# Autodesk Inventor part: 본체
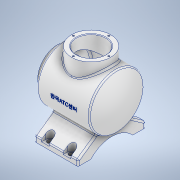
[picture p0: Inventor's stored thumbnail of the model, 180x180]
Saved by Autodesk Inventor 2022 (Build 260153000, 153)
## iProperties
Created: 2023-04
Part Number: 본체
Material: 알루미늄 6061
Document SubType Name: Modeling
Designer: ADMIN_PC
Density: 2.7 g/cm^3
Appearance: 알루미늄 - 평지
Mass: 1296.71 g
Surface Area: 1060.45 cm^2
Volume: 480.264 cm^3
Author: ADMIN_PC
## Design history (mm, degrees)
sketch "스케치1"
  geometry: L1 (-85.64, 0)-(92.662, 0) reference; L2 (0, -20.644)-(0, 92.638) reference; L3 (-48.168, 50)-(48.168, 50); L4 (48.168, 50)-(48.168, 0); L5 (48.168, 0)-(-48.168, 0); L6 (-48.168, 0)-(-48.168, 50); L7 (-48.168, 0)-(-60.168, 0); L8 (-60.168, 0)-(-60.168, 36); L9 (-60.168, 36)-(-48.168, 36); L10 (-48.168, 36)-(-48.168, 0); L11 (48.168, 0)-(59.832, 0); A1 r 113 centre (-53.168, 0) between (59.744, -4.46) and (32.36, 73.851); 3 further points
  constraints: 18 end point, 4 parallel, 4 point on circle, 3 point on line, 2 horizontal, 2 perpendicular, 1 centre point, 1 other
  dimensions: "d1" = 113 radius of A1; "d2" = 108 distance from line of L11.end L6; "d3" = 100 diameter of L3 L5; "d4" = 72 diameter of L9 L5; "d5" = 120 distance from line of L11.end L8
revolve "회전1" sketch "스케치1" stored, may be unused: angle "d6" = 90 deg
sketch "스케치2"
  geometry: L1 (60.168, 36)-(60.168, -36) reference; L2 (82.8, 0)-(-54.4, 0) reference; C1 r 36 at (-1.832, 0); 1 further point
  constraints: 1 centre point, 1 point on line
  dimensions: "d7" = 62 distance from line of L1 C1.centre; "d8" = 72 diameter of C1
extrude "돌출1" join sketch "스케치2" distance "d9" = 65; taper "d10" = 0 deg
node "작업 평면1"
sketch "스케치3"
  geometry: L1 (40.168, 62)-(-39.832, 62); L2 (-39.832, 62)-(-39.832, -62); L3 (-39.832, -62)-(40.168, -62); L4 (40.168, -62)-(40.168, 62); L5 (60.168, 36)-(60.168, -36) reference; L6 (84.168, 0)-(-83.832, 0) reference; 1 further point
  constraints: 8 end point, 2 parallel, 1 horizontal, 1 perpendicular, 1 other
  dimensions: "d12" = 20 distance between parallel lines of L5 L4; "d13" = 124 distance of L3.end L1.start; "d14" = 80 distance between parallel lines of L2 L4
extrude "돌출2" join sketch "스케치3" distance "d15" = 10; taper "d16" = 0 deg
sketch "스케치4"
  geometry: L1 (124, 10)-(0, 10) reference; L2 (0, 10)-(49.774, 44.852); L3 (49.774, 44.852)-(74.226, 44.852); L4 (124, 0)-(124, 10) reference; L5 (74.226, 44.852)-(124, 10); L6 (0, 0)-(0, 10) reference; 1 further point
  constraints: 6 end point, 1 horizontal
  dimensions: "d17" = 55 deg angle of L5 L4; "d18" = 55 deg angle of L2 L6; "d19" = 34.85185 distance between parallel lines of L1 L3
extrude "돌출3" join sketch "스케치4" distance "d20" = 80; taper "d21" = 0 deg
sketch "스케치5"
  geometry: L1 (62, 153.549)-(62, -9.987); L2 (23.5, 0)-(100.5, 0); L3 (100.5, 0)-(100.5, 17); L4 (100.5, 17)-(23.5, 17); L5 (23.5, 17)-(23.5, 0); L6 (124, 0)-(0, 0) reference; A1 r 52.096 centre (62, -35.096) between (100.5, 0) and (23.5, 0); 3 further points
  constraints: 10 end point, 2 parallel, 2 point on circle, 1 centre point, 1 collinear, 1 horizontal, 1 perpendicular, 1 point on line, 1 vertical, 1 other
  dimensions: "d22" = 77 distance between parallel lines of L3 L5; "d23" = 17 distance between parallel lines of L2 L4; "d24" = 52.09559 radius of A1
extrude "돌출4" cut sketch "스케치5" extent not by distance; stored distance "d25" = 0; taper "d26" = 0 deg
node "작업 평면3"
sketch "스케치6"
  geometry: L1 (-19.832, -54)-(-19.832, -74.505); L2 (-12.832, -54)-(-12.832, -74.505); L3 (-26.832, -74.505)-(-26.832, -54); L4 (-39.832, -62)-(40.168, -62) reference; L5 (-39.832, -38.5)-(-39.832, -62) reference; L6 (84.168, 0)-(-83.832, 0) reference; L7 (0, -111.2)-(0, 90.867) reference; L8 (20.168, -54)-(20.168, -74.505); L9 (13.168, -54)-(13.168, -74.505); L10 (27.168, -74.505)-(27.168, -54); L11 (20.168, 54)-(20.168, 74.505); L12 (27.168, 74.505)-(27.168, 54); L13 (-19.832, 54)-(-19.832, 74.505); L14 (-26.832, 74.505)-(-26.832, 54); L15 (13.168, 54)-(13.168, 74.505); L16 (-12.832, 54)-(-12.832, 74.505); A1 r 7 centre (-19.832, -54) between (-12.832, -54) and (-26.832, -54); A2 r 7 centre (-19.832, -74.505) between (-26.832, -74.505) and (-12.832, -74.505); A3 r 7 centre (20.168, -54) between (27.168, -54) and (13.168, -54); A4 r 7 centre (20.168, -74.505) between (13.168, -74.505) and (27.168, -74.505); A5 r 7 centre (20.168, 54) between (13.168, 54) and (27.168, 54); A6 r 7 centre (-19.832, 54) between (-26.832, 54) and (-12.832, 54); A7 r 7 centre (20.168, 74.505) between (27.168, 74.505) and (13.168, 74.505); A8 r 7 centre (-19.832, 74.505) between (-12.832, 74.505) and (-26.832, 74.505); 5 further points
  constraints: 32 end point, 16 point on circle, 14 symmetric about line, 8 centre point, 8 tangent, 2 midpoint, 2 parallel, 2 vertical, 4 other
  dimensions: "d28" = 14 distance between parallel lines of L2 L3; "d29" = 8 distance from line of L4 L1.start; "d30" = 20 distance between parallel lines of L5 L1; "d31" = 20.50493 distance of L3.start L3.end; "d32" = 8 distance from line of L4 L8.start; "d33" = 14 distance between parallel lines of L9 L10; "d34" = 40 distance between parallel lines of L8 L1; "d35" = 20.50493 distance of L10.start L10.end
extrude "돌출5" cut sketch "스케치6" distance "d36" = 20.50493 (= d35); taper "d37" = 0 deg
sketch "스케치7"
  geometry: L1 (-84.168, 0)-(83.832, 0) reference; L2 (0, -105.4)-(0, 93.4) reference; L3 (-60.168, -36)-(-60.168, 36) reference; L4 (-60.168, 0)-(-41.168, 0); L5 (-41.168, 0)-(-41.168, 27); L6 (-41.168, 27)-(-60.168, 27); L7 (-60.168, 27)-(-60.168, 0); L8 (-41.168, 0)-(43.718, 0); L9 (43.718, 0)-(43.718, 43); L10 (43.718, 43)-(-41.168, 43); L11 (-41.168, 43)-(-41.168, 0); L12 (43.718, 0)-(52.832, 0); A1 r 113 centre (-53.168, 0) between (48.168, -50) and (48.168, 50) reference; A2 r 106 centre (-53.168, 0) between (41.891, -46.903) and (41.891, 46.903); 5 further points
  constraints: 18 end point, 4 parallel, 4 point on circle, 2 horizontal, 2 perpendicular, 1 centre point, 1 collinear, 1 midpoint
  dimensions: "d38" = 7 radial gap between concentric circles of A1 A2; "d39" = 19 distance between parallel lines of L11 L3; "d40" = 54 diameter of L6 L1; "d41" = 86 diameter of L10 L1
revolve "회전2" sketch "스케치7" stored, may be unused: angle "d42" = 90 deg
sketch "스케치8"
  geometry: C1 r 36 at (0, 0) reference; C2 r 27 at (0, 0); 1 further point
  constraints: 1 centre point
  dimensions: "d43" = 54 diameter of C2
extrude "돌출6" cut sketch "스케치8" distance "d44" = 65; taper "d45" = 0 deg
sketch "스케치9" dims "d46" = 65
  geometry: L1 (0, -105.4)-(0, 93.4) reference; 3 further points
  constraints: 1 coincident, 1 point on line, 1 vertical alignment, 2 other
hole "구멍1" sketch "스케치9" at (0, 32.5) diameter "d47" = 3.242; stored, may be unused: countersink angle "d51" = 90 deg, drill point angle "d53" = 118 deg; dims "d48" = 8, "d49" = 4, "d50" = 2, "d52" = 10
sketch "스케치10" dims "d57" = 65
  geometry: L1 (0, 0)-(0, 34.763); C1 r 27 at (0, 0) reference; 2 further points
  constraints: 2 end point, 1 point on line, 1 vertical, 1 vertical alignment, 2 other
hole "구멍2" sketch "스케치10" at (0, 32.5) diameter "d58" = 3.242; stored, may be unused: countersink angle "d62" = 90 deg, drill point angle "d64" = 118 deg; dims "d59" = 8, "d60" = 4, "d61" = 2, "d63" = 10
fillet "모깎기1" dims "d68" = 3
chamfer "모따기1" distance "d69" = 1; stored, may be unused: second distance "d70" = 2, angle "d71" = 45 deg
sketch "스케치11"
  geometry: A1 r 7 centre (-20.168, -54) between (-13.168, -54) and (-27.168, -54) reference; A2 r 7 centre (19.832, -54) between (26.832, -54) and (12.832, -54) reference; A3 r 7 centre (19.832, 54) between (12.832, 54) and (26.832, 54) reference; A4 r 7 centre (-20.168, 54) between (-27.168, 54) and (-13.168, 54) reference; 5 further points
  constraints: 4 coincident
hole "구멍3" sketch "스케치11" at (19.832, 54), (-20.168, 54), (-20.168, -54), (19.832, -54) diameter "d72" = 9; stored, may be unused: countersink angle "d76" = 90 deg, drill point angle "d78" = 118 deg; dims "d73" = 8, "d74" = 4, "d75" = 2, "d77" = 10
node "작업 평면4"
sketch "스케치12"
  geometry: L1 (-60.168, -36)-(-60.168, 36) reference; L2 (-84.168, 0)-(83.832, 0) reference; 2 further points
  constraints: 1 point on line, 1 other
  dimensions: "d79" = 62 distance from line of L1 point (1.832, 0)
feature "엠보싱1" sketch "스케치12" dims "d1" = 113, "d2" = 108, "d3" = 100, "d4" = 72, "d5" = 120, "d80" = 0.5, "d81" = 0
node "솔리드1"
pattern_circular "원형 패턴1" dims angle "d55" = 360 deg
pattern_circular "원형 패턴2" dims angle "d66" = 360 deg
feature "A9D066F2-1C7D-4E18-AEED-F7BC21143FA4" dims "d72" = 9, "d73" = 8, "d74" = 4, "d75" = 2, "d76" = 90 deg, "d77" = 10, "d78" = 118 deg
other parameters: "d11" = -77, "d27" = -71
